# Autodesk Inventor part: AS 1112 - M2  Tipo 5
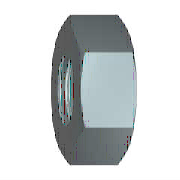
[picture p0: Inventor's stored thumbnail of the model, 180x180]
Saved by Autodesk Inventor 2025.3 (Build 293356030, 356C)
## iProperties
Created: 2024-01
Part Number: AS 1112 - M2  Tipo 5
Material: Acciaio, Dolce
Description: Dadi esagonali metrici ISO, inclusi dadi sottili, dadi con intaglio e dadi a corona
Document SubType Name: Modeling
Standard: AS 1112
Designer: R5800u
Standards Organization: AS
Language: it-IT
Size Designation: M2  Tipo 5
Categories: <MemberInstance><Categories><Category DisplayName="Elementi di fissaggio" InternalName="e4da775c-781d-43d5-af7c-5136215cf5a6" Mnemonic="FSTN"><Category DisplayN
Density: 7.85 g/cm^3
Appearance: Semilucidato
IsCustomPart: 0
Author: R5800u
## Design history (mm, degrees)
body "Solid1"
workaxis "Work Axis1"
workplane "Work Plane1"
sketch "Schizzo1"
  geometry: L1 (-2.309, 0)-(-1.155, 2); L2 (-1.155, 2)-(1.155, 2); L3 (1.155, 2)-(2.309, 0); L4 (2.309, 0)-(1.155, -2); L5 (1.155, -2)-(-1.155, -2); L6 (-1.155, -2)-(-2.309, 0); 2 further points
  constraints: 12 end point, 1 coincident, 1 horizontal, 11 other
  dimensions: "d0" = 4.6188 distance of L3.end L1.start (= 1.1547 x SW)
extrude "Corpo" new body sketch "Schizzo1" distance "d1" = 1.6 (= KOH); taper "d2" = 0 deg
revolve "Smusso1" stored, may be unused: angle "d7" = 90 deg
sketch "Schizzo3"
  geometry: A1 r 2 centre (0, 0) between (-1, -1.732) and (1, -1.732) reference; 1 further point
  constraints: 1 coincident
hole "Filettatura" sketch "Schizzo3" diameter "d25" = 1.567; stored, may be unused: countersink angle "d29" = 82 deg, drill point angle "d31" = 118 deg; dims "d26" = 6, "d27" = 4, "d28" = 2, "d30" = 8
chamfer "Smusso2" distance "d8" = 0.21651 (= -0.5 x GD1 + 0.5 x NND); stored, may be unused: angle "d9" = 30 deg, second distance "d40" = 0.21651 (= -0.5 x GD1 + 0.5 x NND)
chamfer "Smusso3" distance "d10" = 0.21651 (= -0.5 x GD1 + 0.5 x NND); stored, may be unused: angle "d11" = 30 deg, second distance "d41" = 0.21651 (= -0.5 x GD1 + 0.5 x NND)
sketch "Schizzo2"
  geometry: L1 (0, 1.155)-(0, 2.309) reference; L2 (0, 2.309)-(1.6, 2.309) reference; L3 (1.6, 1.155)-(1.6, 2.309) reference; L4 (-0.32, 0)-(1.92, 0) reference; L5 (0.179, 2.309)-(0, 2); L6 (1.421, 2.309)-(1.6, 2)
  constraints: 4 end point, 4 point on line
  dimensions: "d3" = 30 deg angle of L1 L5 (= ANG1); "d4" = 30 deg angle of L3 L6 (= ANG2); "d5" = 4 diameter of L5.end L4 (= SW0); "d6" = 4 diameter of L6.end L4 (= SW01)
other parameters: "ANG1" = 30 deg [user parameter; used in 1 equation term], "ANG2" = 30 deg [user parameter; used in 1 equation term], "NND" = 2 [user parameter; used in 4 equation terms], "KOH" = 1.6 [user parameter; used in 1 equation term], "SW" = 4 [user parameter; used in 4 equation terms], "SW0" = 4 (= SW) [user parameter; used in 1 equation term], "SW01" = 4 (= SW) [user parameter; used in 1 equation term], "GD1" = 1.56699 (computed from THREADDIA, PTC, TOA) [user parameter; used in 4 equation terms], "d13" = 0, "d14" = 0, "d39" = 0, "d42" = 0, "GUL" = 0.21651 (= 0.541266 x PTC) [user parameter], "TPU" = 25 (computed from PTC) [user parameter], "WFT" = 0 [user parameter], "THREADDIA" = 2 [user parameter; used in 1 equation term], "TOA" = 30 deg [user parameter; used in 1 equation term], "PTC" = 0.4 [user parameter; used in 4 equation terms], "E0" = 4.62 (= 1.155 x SW) [user parameter], "GAL" = 0.21651 (= 0.541266 x PTC) [user parameter]
